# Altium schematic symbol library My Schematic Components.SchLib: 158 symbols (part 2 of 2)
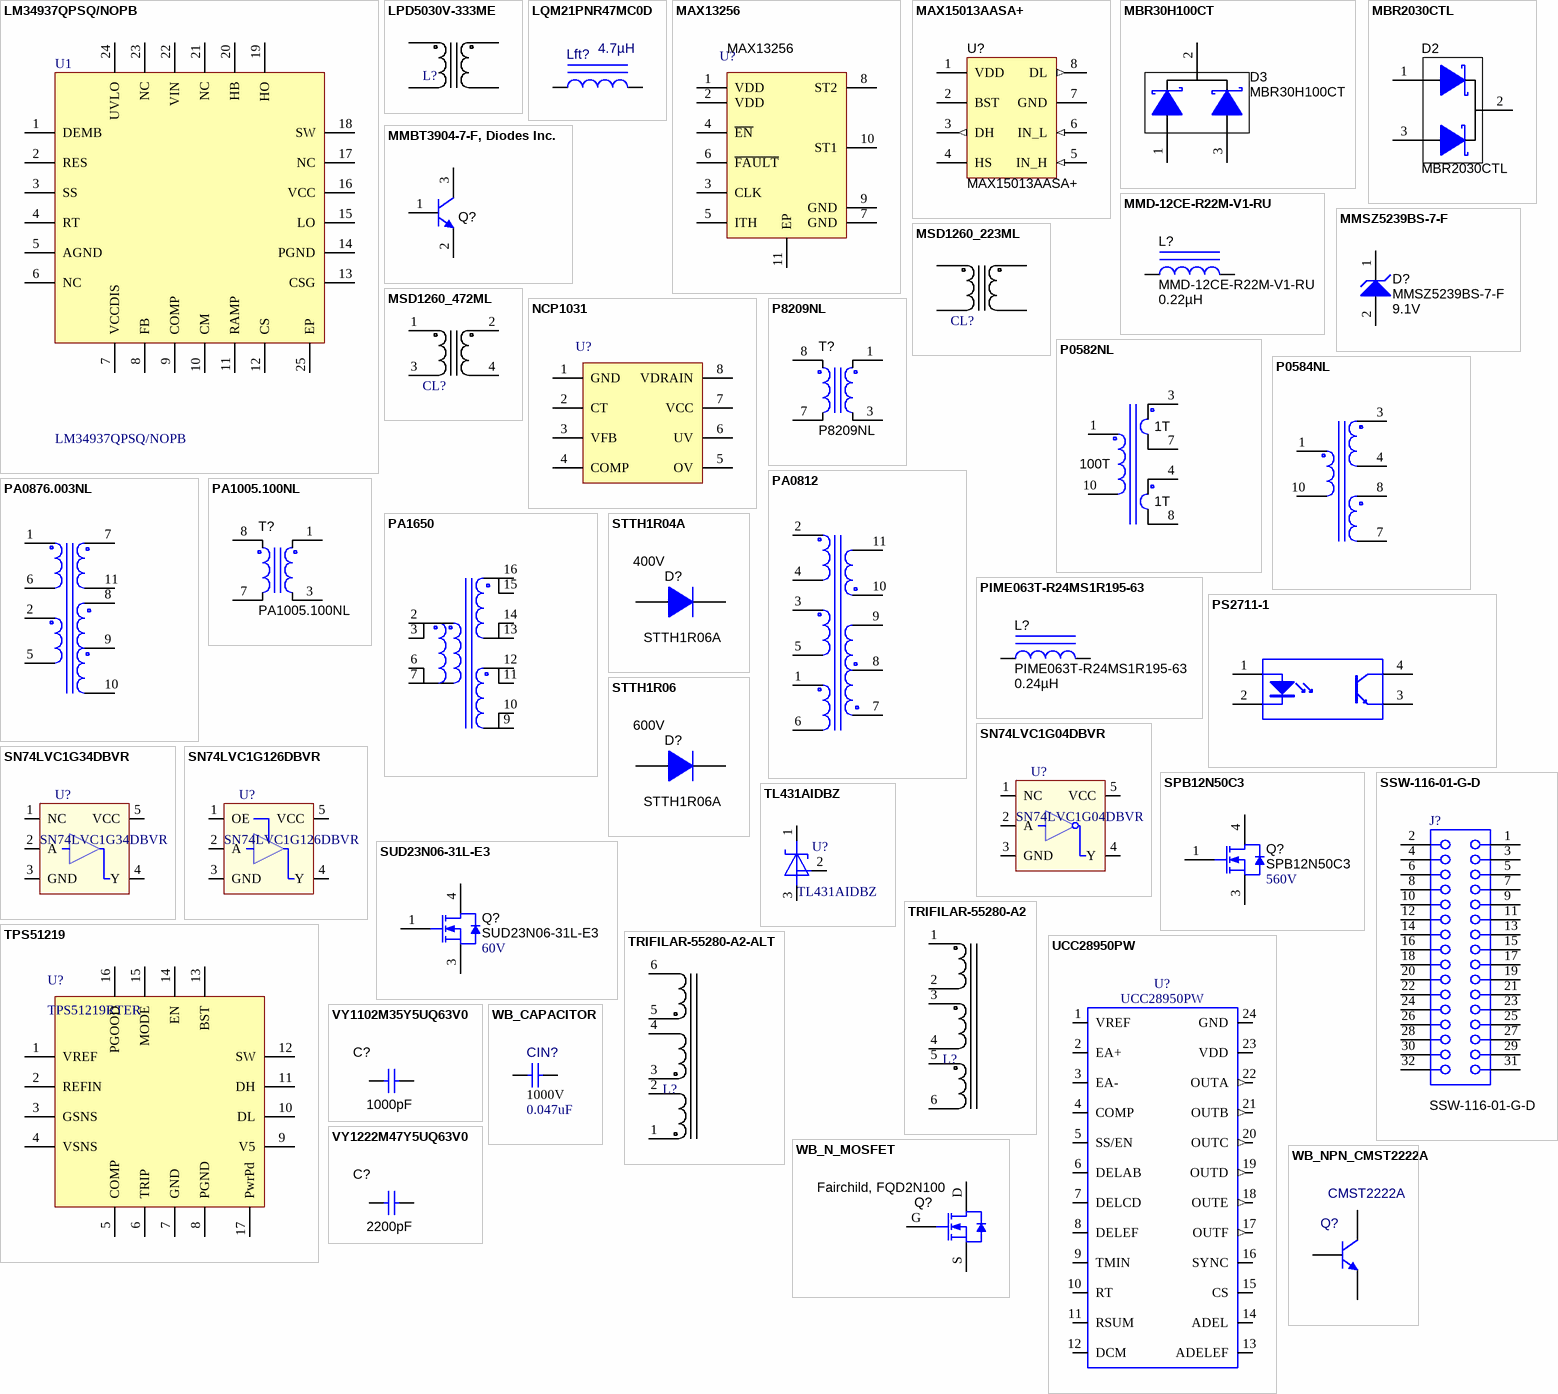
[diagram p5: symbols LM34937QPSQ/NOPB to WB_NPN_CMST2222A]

## SSW-116-01-G-D
designator J?
Receptacle 100mil 16x2, Gold, TH; Manufacturer: SAMTEC
footprint CONN_SSW-116-01-G-D (SAMTEC 16x2, 100mil, female, TH)
pins: 1, 2, 3, 4, 5, 6, 7, 8, 9, 10, 11, 12, 13, 14, 15, 16, 17, 18, 19, 20, 21, 22, 23, 24, 25, 26, 27, 28, 29, 30, 31, 32

## STTH1R04A
designator D?, comment STTH1R06A  Value2: 400V
Diode, Ultrafast, 400V, 1A, SMA; Manufacturer: ST; Vf_V: 1.0; Io_A: 1; Vr_V: 400; TJmax_C: 175; RJC_CperW: 30; Current - Reverse Leakage @ Vr: 5µA @ 400V; Speed: Fast Recovery =< 500ns, > 200mA (Io); Reverse Recovery Time (trr): 45ns; Value: 1.0V
signal-integrity model Diode
footprint SMA - HV (Molded Diode, 2-Leads, Body 4.3x2.6mm. Based on STTH1R06 footprint dimensions and land pattern for 600V.)
pins: 1 K, 2 A

## STTH1R06
designator D?, comment STTH1R06A  Value2: 600V
Diode, Ultrafast, 600V, 1A, SMA; Manufacturer: ST; Vf_V: 1.0; Io_A: 1; Vr_V: 600; TJmax_C: 175; RJC_CperW: 30; Current - Reverse Leakage @ Vr: 1µA @ 600V; Speed: Fast Recovery =< 500ns, > 200mA (Io); Reverse Recovery Time (trr): 45ns; Value: 1.0V
signal-integrity model Diode
footprint SMA - HV (Molded Diode, 2-Leads, Body 4.3x2.6mm. Based on STTH1R06 footprint dimensions and land pattern for 600V.)
pins: 1 K, 2 A

## SUD23N06-31L-E3
designator Q?  value 60V
MOSFET, N-CH, 60V, 23A, DPAK; Manufacturer: Vishay  Siliconix; ChType: N; VdsMax_V: 60; Value1: 0.031 ohm; Value2: 11 nC; QgTyp_nC: 11; Vgs_V: 20; IdsMax_A: 23
footprint DPAK
pins: 1 G, 3 S, 4 D

## TL431AIDBZ
designator U?
IC, Precision Adjustable Shunt Regulator; Manufacturer: Texas Instruments; Area: 16384; Reference: \\vette02\pmp_pcb\pcad_pdf's\TL431A-B.pdf; Second_Source: C:\program files\p-cad 2004\pcad_pdf's\TL431A-B.pdf; PCB DECAL: SOT-23
footprint SOT-23 (Footprint not found)
footprint SOT-23L (Footprint not found)
footprint SOT-23M (Footprint not found)
pins: 1 C, 2 REF, 3 A

## TPS51219
designator U?, comment TPS51219RTER
Single-Synchronous Step-Down Controller, 16-pin QFN; Manufacturer: Texas Instruments; PowerWise: Y; CompType: Switcher
footprint S-PWQFN-N16 (QFN, 16-Leads, Body 3x3mm, Pitch 0.5mm, TI Recommended)
pins: 1 VREF, 2 REFIN, 3 GSNS, 4 VSNS (power), 5 COMP, 6 TRIP, 7 GND (power), 8 PGND, 9 V5, 10 DL, 11 DH, 12 SW, 13 BST, 14 EN, 15 MODE, 16 PGOOD, 17 PwrPd

## TRIFILAR-55280-A2
designator L?  (value not drawn)
Coupled Inductor; Manufacturer: Custom; L (uH): 20; DCR: 0.05; Isat (A): 0.8
footprint TRIFILAR-55280-A2
pins: 1, 2, 3, 4, 5, 6

## TRIFILAR-55280-A2-ALT
designator L?  (value not drawn)
Coupled Inductor; Manufacturer: Custom; L (uH): 20; DCR: 0.05; Isat (A): 0.8
footprint TRIFILAR-55280-A2
pins: 1, 2, 3, 4, 5, 6

## UCC28950PW
designator U?
IC,  Advanced Phase-Shifted PWM Controller; Manufacturer: Texas Instruments; AREA: 117120; Reference: \\vette02\pmp_pcb\pcad_pdf's\ucc28950.pdf; Second_Source: C:\program files\p-cad 2004\pcad_pdf's\ucc28950.pdf; PCB DECAL: PW24
footprint PW024 (Shrink Small Outline; 24 Leads; Body Width 4.4 mm; Pitch 0.65 mm)
pins: 1 VREF (power), 2 EA+, 3 EA-, 4 COMP, 5 SS/EN, 6 DELAB, 7 DELCD, 8 DELEF, 9 TMIN, 10 RT, 11 RSUM, 12 DCM, 13 ADELEF, 14 ADEL, 15 CS, 16 SYNC (io), 17 OUTF (out), 18 OUTE (out), 19 OUTD (out), 20 OUTC (out), 21 OUTB (out), 22 OUTA (out), 23 VDD (power), 24 GND (power)

## VY1102M35Y5UQ63V0
designator C?  value 1000pF  (hidden comment: VY1102M35Y5UQ63V0)
CAP, CERM, 1000pF, 500VAC, X1/Y1, RAD; Manufacturer: Vishay/BC Components; Polarized: N; TaMax_C: 125; TaMin_C: -40; Tolerance_%: 20; CompType: Capacitor; Dielectric: Y5U; Ratings: X1Y1
simulation model Capacitor
signal-integrity model Cap
footprint CAPRD10-9X5 (Capacitor, Ceramic, Thru-Hole, Disc; Body 9 x 5 mm (LxW max) Pin Spacing 10 mm (typ))
pins: 1, 2
1 alternate drawing of the same symbol

## VY1222M47Y5UQ63V0
designator C?  value 2200pF  (hidden comment: VY1222M47Y5UQ63V0)
CAP, CERM, 2200pF, 500VAC, X1/Y1, RAD; Manufacturer: Vishay/BC Components; Polarized: N; TaMax_C: 125; TaMin_C: -40; Tolerance_%: 20; CompType: Capacitor; Dielectric: Y5U; Ratings: X1Y1
simulation model Capacitor
signal-integrity model Cap
footprint CAPRD10-12X5 (Capacitor, Ceramic, Thru-Hole, Disc; Body 12 x 5 mm (LxW max) Pin Spacing 10 mm (typ))
pins: 1, 2
1 alternate drawing of the same symbol

## WB_CAPACITOR
designator CIN?, comment value 0.047uF  VDC_V: 1000V  (hidden comment: Kemet, C1812V473KDRACTU)
Capacitor; Polarized: N
simulation model Capacitor
footprint 0603 (0603 from SM-752 data)
footprint 0402 (0402 from SM-752 data)
footprint 0805 (0805 from SM-752 data)
footprint 1206 (1206 from SM-752 data)
footprint 0201 (Data from Panasonic ERJ resistor datasheet dated February 2006)
footprint 0603L (0603 from SM-752 data)
footprint 0402L (0402 from SM-752 data)
footprint 0805L (0805 from SM-752 data)
footprint 1206L (1206 from SM-752 data)
footprint 0603M (0603 from SM-752 data)
footprint 0402M (0402 from SM-752 data)
footprint 0805M (0805 from SM-752 data)
footprint 1206M (1206 from SM-752 data)
footprint 1812
pins: 1, 2

## WB_N_MOSFET
designator Q?, comment Fairchild, FQD2N100
N-Channel MOSFET
simulation model NMOS (Altium default N-channel MOSFET)
footprint DPAK (D-PAK, 3-Pads, Body 6.2x6.7mm (max), IPC Medium Density_modified 2008-05-02 to match OnSemi land pattern)
pins: D, G, S

## WB_NPN_CMST2222A
designator Q?, comment CMST2222A
NPN Bipolar Transistor
simulation model NPN (Model Description)
footprint SOT-23 (SOT23, 3-Leads, Body 3.0x2.6mm (max), Pitch 0.95mm, IPC Medium Density, from National MF03A)
pins: 1 B, 2 E, 3 C

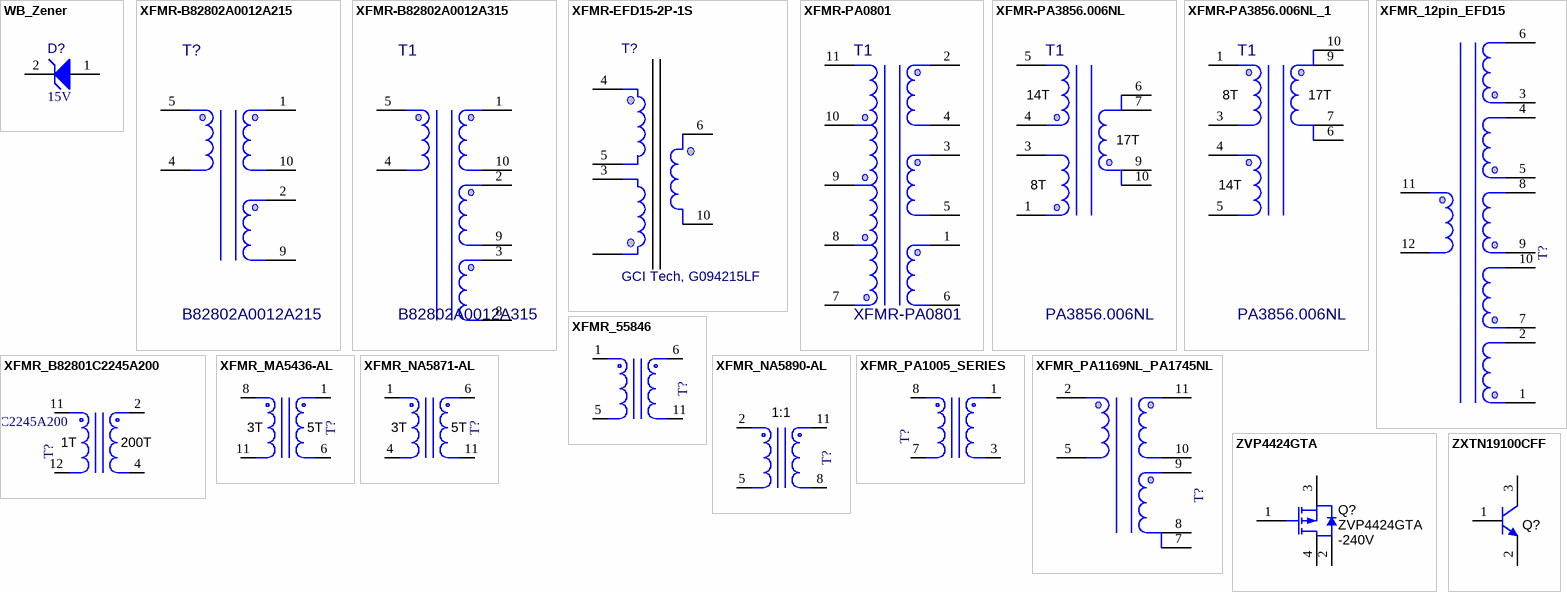
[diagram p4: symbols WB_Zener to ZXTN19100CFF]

## WB_Zener
designator D?, comment value 15V  (hidden comment: CMZ5929B)
Manufacturer: Central Semiconductor; Manufacturer_PN: CMZ5931B; CompType: Zener
simulation model Zener (Altium default Zener diode model)
footprint SMA (Molded Diode, 2-Leads, Body 4.3x2.6mm, IPC Medium Density, based on OnSemi component dimensions and land pattern)
pins: 1 A, 2 K

## XFMR-B82802A0012A215
designator T?, comment B82802A0012A215
SMT Power Transformer; Manufacturer: EPCOS; Value: 1:2.25:6.5; L (uH): 100; DCR: 0.03
footprint XFMR_B82802A0012A215 (Recommended land pattern for EPCOS EFD15 B82802A0012A215/315 transformer)
pins: 1, 2, 4, 5, 9, 10

## XFMR-B82802A0012A315
designator T1, comment B82802A0012A315
SMT Power Transformer; Manufacturer: EPCOS; Value: 1:2.5:0.75:7.5; L (uH): 100; DCR: 0.05
footprint XFMR_B82802A0012A215 (Recommended land pattern for EPCOS EFD15 B82802A0012A215/315 transformer)
pins: 1, 2, 3, 4, 5, 8, 9, 10

## XFMR-EFD15-2P-1S
designator T?, comment GCI Tech, G094215LF
footprint G094215LF r 0
pins: 1, 3, 4, 5, 6, 10

## XFMR-PA0801
designator T1
footprint pa080X
footprint PA0901
pins: 1, 2, 3, 4, 5, 6, 7, 8, 9, 10, 11

## XFMR-PA3856.006NL
designator T1, comment PA3856.006NL
SMT Power Transformer; Manufacturer: Pulse Engineering; Value: 8T : 17T : 14T
footprint XFMR_PA3856.006NL (Recommended land pattern for Pulse Engineering PA3856.006NL transformer)
pins: 1, 3, 4, 5, 6, 7, 9, 10

## XFMR-PA3856.006NL_1
designator T1, comment PA3856.006NL
SMT Power Transformer; Manufacturer: Pulse Engineering; Value: 8T : 17T : 14T
footprint XFMR_PA3856.006NL (Recommended land pattern for Pulse Engineering PA3856.006NL transformer)
pins: 1, 3, 4, 5, 6, 7, 9, 10

## XFMR_12pin_EFD15
designator T?, comment PA1169NL/PA1745NL  (value not drawn)
XFMR; Area: 378.4 sq. mm
footprint XFMR_Pulse_EFD15_SMT (Recommended land pattern for Pulse EFD 15 Platforms - SMT)
pins: 1, 2, 3, 4, 5, 6, 7, 8, 9, 10, 11, 12

## XFMR_55846
designator T?  (value not drawn)
XFMR, SMT 800W; Manufacturer: Payton; PartNumber: 55846; Area: 896 mm; Reference: \\vette02\pmp_pcb\pcad_pdf's\55846.pdf; Second Source: C:\program files\p-cad 2004\pcad_pdf's\55846.pdf; PCB DECAL: IND_PAYTON26.5X31MM; Value: x uH
pins: 1, 5, 6, 11

## XFMR_B82801C2245A200
designator T?, comment B82801C2245A200
Transformer, Current Sense 1T:200T; Manufacturer: Epcos; Value: 22.4 mH; Area: 191.4 sq. mm; Reference: \\vette02\pmp_pcb\pcad_pdf's\xxxxxx.pdf; Second_Source: C:\program files\p-cad 2004\pcad_pdf's\PA1005 SERIES.pdf; Type: B82801C EE12.6
footprint XFMR_B82801C (Recommended land pattern for EPCOS B82801C transformer)
pins: 2, 4, 11, 12

## XFMR_MA5436-AL
designator T?  (value not drawn)
XFMR, SMT 800W 3T:5T; Manufacturer: Coilcraft; Area: 1159 sq. mm; Reference: \\vette02\pmp_pcb\pcad_pdf's\MA5436-AL.pdf; Second Source: C:\program files\p-cad 2004\pcad_pdf's\55846.pdf; Value: 49.5 uH
pins: 1, 6, 8, 11

## XFMR_NA5871-AL
designator T?, comment NA5871-AL  (value not drawn)
XFMR, SMT 800W 3T:5T; Manufacturer: Coilcraft; Area: 1586 sq. mm; Reference: \\vette02\pmp_pcb\pcad_pdf's\NA5871-AL.pdf; Second Source: C:\program files\p-cad 2004\pcad_pdf's\NA5871-AL.pdf; Value: 42 uH min
footprint XFMR_NA5871-AL (Recommended land pattern for Coilcraft NA5871-AL transformer)
pins: 1, 4, 6, 11

## XFMR_NA5890-AL
designator T?, comment NA5890-AL  (value not drawn)
XFMR, SMT 50uH 1:1 2250VDC; Manufacturer: Coilcraft; Area: 378.4 sq. mm; Reference: \\vette02\pmp_pcb\pcad_pdf's\NA5890-AL.pdf; Second Source: C:\program files\p-cad 2004\pcad_pdf's\NA5890-AL.pdf
footprint XFMR_NA5890-AL (Recommended land pattern for Coilcraft NA5890-AL transformer)
pins: 2, 5, 8, 11

## XFMR_PA1005_SERIES
designator T?  (value not drawn)
Transformer, Current Sense; Manufacturer: Pulse; PartNumber: 50A, 100:1; Value: 100 to 1; Area: 120960; Reference: \\vette02\pmp_pcb\pcad_pdf's\PA1005 SERIES.pdf; Second_Source: C:\program files\p-cad 2004\pcad_pdf's\PA1005 SERIES.pdf; Type: XFMR_PA1005 SERIES; PCB DECAL: IND_PA_284X330
pins: 1, 2 NOT_CONNECTED_SIGNAL_PIN (power) hidden to NOT_CONNECTED_SIGNAL_PIN, 3, 4 NOT_CONNECTED_SIGNAL_PIN (power) hidden to NOT_CONNECTED_SIGNAL_PIN, 5 NOT_CONNECTED_SIGNAL_PIN (power) hidden to NOT_CONNECTED_SIGNAL_PIN, 6 NOT_CONNECTED_SIGNAL_PIN (power) hidden to NOT_CONNECTED_SIGNAL_PIN, 7, 8

## XFMR_PA1169NL_PA1745NL
designator T?, comment PA1169NL/PA1745NL  (value not drawn)
XFMR, SMT 38uH, 1:4:4, 3:1:1; Manufacturer: Pulse; Area: 378.4 sq. mm
footprint XFMR_Pulse_EFD15_SMT (Recommended land pattern for Pulse EFD 15 Platforms - SMT)
pins: 2, 5, 7, 8, 9, 10, 11

## ZVP4424GTA
designator Q?  value -240V
MOSFET P-CH 240V 480MA SOT223; Manufacturer: Diodes / Zetex; U/M: EA; ChType: P; VdsMax_V: -240; Vgs_V: -20; Configuration: Single Dual Drain; Continuous Drain Current: - 480 mA; Drain-Source Breakdown Voltage: - 240 V; Gate-Source Breakdown Voltage: +/- 40 V; Power Dissipation: 2.5 W; Resistance Drain-Source RDS (on): 11 Ohms; Transistor Polarity: P-Channel; Fall Time: 20 ns; Rise Time: 8 ns; Typical Turn-Off Delay Time: 26 ns
footprint MP04A_L (SOT223, 4-Leads, Body 6.5x3.5mm, Pitch 2.3mm, Lead Span 7mm, IPC High Density)
footprint MP04A_M (SOT223, 4-Leads, Body 6.5x3.5mm, Pitch 2.3mm, Lead Span 7mm, IPC Low Density)
footprint MP04A_N (SOT223, 4-Leads, Body 6.5x3.5mm, Pitch 2.3mm, Lead Span 7mm, IPC Medium Density)
pins: 1 G, 2 D, 3 S, 4 D

## ZXTN19100CFF
designator Q?, comment ZXTN19100CFFTA  (value not drawn)
Transistor, NPN, 100V, 4.5A, SOT-23; Manufacturer: Diodes Inc.; Alternate Manufacturer: None; CompType: BJT; U/M: EA; PNP: 0; NPN: 1; Vceo_V: 100; Vcesat1_V: 0.235; Value: 0.235V; IcRated_A: 4.5; HfeMax: 500
footprint SOT-23
footprint SOT-23M
footprint SOT-23L
pins: 1 B, 2 E, 3 C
